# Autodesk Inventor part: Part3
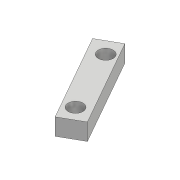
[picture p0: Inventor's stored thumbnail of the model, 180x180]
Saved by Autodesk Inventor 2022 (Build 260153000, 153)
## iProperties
Created: 2017-05
Part Number: Part3
Material: Generic
Document SubType Name: Modeling
Designer: CADCIM 00
Density: 1 g/cm^3
Appearance: Default
Author: CADCIM 00
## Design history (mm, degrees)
sketch "Sketch1"
  geometry: L1 (-30.267, 40.394)-(-1.138, -10.969); L2 (-1.138, -10.969)-(11.085, -4.037); L3 (11.085, -4.037)-(-18.043, 47.326); L4 (-18.043, 47.326)-(-30.267, 40.394); C1 r 4.406 at (-18.304, 36.224) reference; C2 r 4.406 at (0, 0) reference; 1 further point
  constraints: 8 end point, 2 parallel, 1 perpendicular
extrude "Extrusion1" new body sketch "Sketch1" distance "d0" = 10; taper "d1" = 0 deg
body "Solid1"
node "Reference1"
node "Reference2"
